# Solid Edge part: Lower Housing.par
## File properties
Author: CADCIM
Template: NORMENG.PAR
Last saved by: CADCIM
Revision: 12
Application: Solid Edge
Accuracy: 0.99
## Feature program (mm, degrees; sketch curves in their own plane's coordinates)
sketch for "unnamed Protrusion 1" plane through (0, 0, 0) normal (0, -1, 0) x-axis (1, 0, 0)
  line (0, 0) -> (-190.5, 0)
  line (-190.5, 0) -> (-190.5, -10.414)
  line (-190.5, -10.414) -> (-152.4, -10.414)
  arc centre (-0.1761, -3.0894) radius 152.4 from (-88.9, -127) to (-152.4, -10.414) cw
  line (-88.9, -127) -> (-177.8, -127)
  line (-177.8, -127) -> (-177.8, -165.1)
  line (-177.8, -165.1) -> (0, -165.1)
  line (177.8, -165.1) -> (0, -165.1)
  line (177.8, -127) -> (177.8, -165.1)
  line (88.9, -127) -> (177.8, -127)
  arc centre (0.1761, -3.0894) radius 152.4 from (88.9, -127) to (152.4, -10.414) ccw
  line (190.5, -10.414) -> (152.4, -10.414)
  line (190.5, 0) -> (190.5, -10.414)
  line (0, 0) -> (190.5, 0)
extrude "unnamed Protrusion 1" add finite 203.2 symmetric
sketch for "RevolvedCutout_1" plane through (0, 0, 0) normal (0, 0, 1) x-axis (0, 1, 0)
  line (-95.25, 0) -> (95.25, 0)
  line (95.25, 0) -> (95.25, 146.05)
  line (95.25, 146.05) -> (-95.25, 146.05)
  line (-95.25, 146.05) -> (-95.25, 0)
  dimension (linear) = 95.25
revolve "RevolvedCutout_1" cut finite 180 deg
sketch for "unnamed Cutout 1" plane through (0, -101.6, -82.55) normal (0, -1, 0) x-axis (1, 0, 0)
  arc centre (0, 82.55) radius 123.825 from (123.825, 82.55) to (-123.825, 82.55) cw
  line (-123.825, 82.55) -> (123.825, 82.55)
extrude "unnamed Cutout 1" cut through along -normal
sketch for "unnamed Cutout 2" plane through (0, 101.6, -82.55) normal (0, 1, 0) x-axis (-1, 0, 0)
  arc centre (0, 82.55) radius 38.1 from (38.1, 82.55) to (-38.1, 82.55) cw
  line (-38.1, 82.55) -> (38.1, 82.55)
extrude "unnamed Cutout 2" cut through along -normal
sketch for "Hole_1" plane through (114.3, 0, 0) normal (0, 0, 1) x-axis (0, 1, 0)
  hole centre (-76.2, -57.15) bore radius 5.207
hole "Hole_1" diameter 10.414 through
pattern "unnamed Pattern 1" of "Hole_1"
pattern "unnamed Pattern 2"
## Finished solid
Body 1: solid body, 28 faces, 70 edges, 36 vertices.
  Faces by surface: plane 15, cylinder 13
  Edges by curve: line 44, circle 26
Bounding box of the edges (mm): 381.000 x 203.200 x 165.100, from (-190.5, -101.6, -165.1) to (190.5, 101.6, 0).
Cylindrical faces by radius (mm): R5.207 x8, R38.1 x1, R123.825 x1, R146.05 x1, R152.4 x2
Planar faces by outward normal: +x 2, +y 2, +z 4, -x 2, -y 2, -z 3
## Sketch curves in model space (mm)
line (190.5, 0, 0) -> (190.5, 0, -10.414)
line (190.5, 0, -10.414) -> (152.4, 0, -10.414)
arc centre (0.1761, 0, -3.0894) radius 152.4 from (88.9, 0, -127) through (134.012, 0, -75.9848) to (152.4, 0, -10.414)
line (88.9, 0, -127) -> (177.8, 0, -127)
line (177.8, 0, -127) -> (177.8, 0, -165.1)
line (177.8, 0, -165.1) -> (0, 0, -165.1)
line (-177.8, 0, -165.1) -> (0, 0, -165.1)
line (-177.8, 0, -127) -> (-177.8, 0, -165.1)
line (-88.9, 0, -127) -> (-177.8, 0, -127)
arc centre (-0.1761, 0, -3.0894) radius 152.4 from (-88.9, 0, -127) through (-134.012, 0, -75.9848) to (-152.4, 0, -10.414)
line (-190.5, 0, -10.414) -> (-152.4, 0, -10.414)
line (-190.5, 0, 0) -> (-190.5, 0, -10.414)
line (0, 0, 0) -> (-190.5, 0, 0)
line (0, 0, 0) -> (190.5, 0, 0)
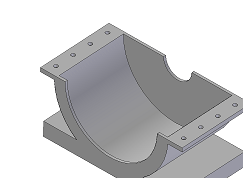
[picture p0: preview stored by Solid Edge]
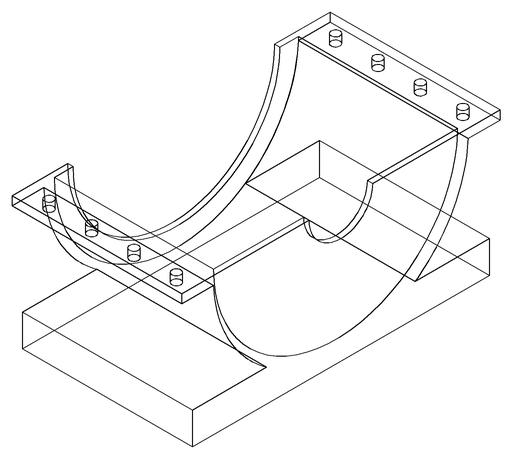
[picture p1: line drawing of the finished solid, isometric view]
